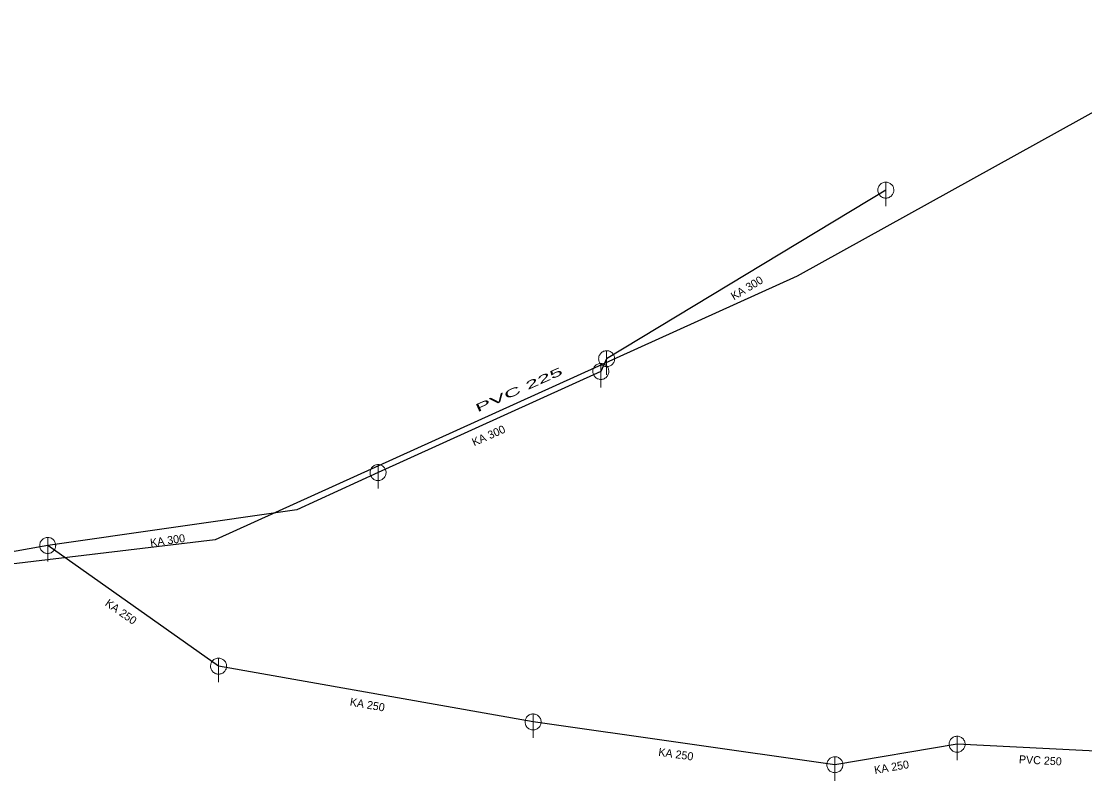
# Model space of a CAD drawing. Extents: x -659250 to -657316, y -997555 to -993684.
# Drawn here: x -658412.5 to -658279.6, y -995142.2 to -995047.3 of the extents above; entities that cross this region are included whole.
import ezdxf

# ---------------------------------------------------------------- set-up
doc = ezdxf.new("R2010")
doc.units = 0
doc.header["$LTSCALE"] = 0.4
doc.layers.add('1', color=7, linetype='Continuous')
for name, color, linetype, lineweight in [('14', 7, 'Continuous', 25), ('17', 7, 'Continuous', 25), ('22', 7, 'Continuous', 13)]:
    doc.layers.add(name, color=color, linetype=linetype, lineweight=lineweight)

msp = doc.modelspace()

# ---------------------------------------------------------------- linework, layer by layer
at = {"layer": '14'}
for p, q in [((-658304.458, -995068.407), (-658339.359, -995089.46)), ((-658339.359, -995089.46), (-658340.085, -995091.051)), ((-658340.085, -995091.051), (-658367.932, -995103.685)), ((-658409.23, -995112.789), (-658422.21, -995115.16)), ((-658272.949, -995138.75), (-658295.55, -995137.62))]:
    msp.add_line(p, q, dxfattribs=at)
for points in [[(-658367.932, -995103.685), (-658378.086, -995108.348), (-658409.23, -995112.789)], [(-658348.55, -995134.84), (-658387.87, -995127.87), (-658409.23, -995112.789)], [(-658295.55, -995137.62), (-658310.829, -995140.18), (-658348.55, -995134.84)]]:
    msp.add_lwpolyline(points, dxfattribs=at)
at = {"layer": '17'}
msp.add_lwpolyline([(-658259.263, -995047.311), (-658274.545, -995056.438), (-658315.531, -995079.142), (-658388.274, -995112.102), (-658418.381, -995115.664), (-658425.669, -995116.129), (-658489.359, -995122.5)], dxfattribs=at)
at = {"layer": '22'}
for p, q in [((-658304.459, -995070.407), (-658304.458, -995067.407)), ((-658339.359, -995091.46), (-658339.358, -995088.46)), ((-658340.085, -995093.051), (-658340.084, -995090.051)), ((-658367.932, -995105.685), (-658367.931, -995102.685)), ((-658409.23, -995114.79), (-658409.229, -995111.79)), ((-658387.87, -995129.87), (-658387.869, -995126.87)), ((-658348.55, -995136.84), (-658348.549, -995133.84)), ((-658295.55, -995139.62), (-658295.549, -995136.62)), ((-658310.83, -995142.18), (-658310.829, -995139.18))]:
    msp.add_line(p, q, dxfattribs=at)
for points in [[(-658303.459, -995068.407), (-658303.464, -995068.298), (-658303.482, -995068.19), (-658303.512, -995068.084), (-658303.552, -995067.983), (-658303.604, -995067.886), (-658303.666, -995067.796), (-658303.738, -995067.713), (-658303.818, -995067.639), (-658303.906, -995067.573), (-658304, -995067.518), (-658304.1, -995067.473), (-658304.205, -995067.44), (-658304.312, -995067.418), (-658304.421, -995067.408), (-658304.531, -995067.41), (-658304.639, -995067.424), (-658304.746, -995067.449), (-658304.849, -995067.486), (-658304.947, -995067.535), (-658305.039, -995067.593), (-658305.125, -995067.662), (-658305.202, -995067.739), (-658305.271, -995067.825), (-658305.33, -995067.917), (-658305.378, -995068.015), (-658305.415, -995068.118), (-658305.441, -995068.225), (-658305.455, -995068.333), (-658305.458, -995068.443), (-658305.448, -995068.552), (-658305.427, -995068.659), (-658305.393, -995068.763), (-658305.349, -995068.863), (-658305.294, -995068.958), (-658305.228, -995069.046), (-658305.154, -995069.126), (-658305.071, -995069.198), (-658304.981, -995069.26), (-658304.885, -995069.312), (-658304.783, -995069.353), (-658304.678, -995069.383), (-658304.57, -995069.401), (-658304.46, -995069.407), (-658304.351, -995069.401), (-658304.243, -995069.383), (-658304.138, -995069.354), (-658304.036, -995069.313), (-658303.939, -995069.261), (-658303.849, -995069.199), (-658303.766, -995069.128), (-658303.691, -995069.048), (-658303.626, -995068.96), (-658303.57, -995068.866), (-658303.526, -995068.766), (-658303.492, -995068.662), (-658303.47, -995068.554), (-658303.46, -995068.445)], [(-658338.359, -995089.46), (-658338.364, -995089.351), (-658338.382, -995089.243), (-658338.412, -995089.137), (-658338.452, -995089.036), (-658338.504, -995088.939), (-658338.566, -995088.849), (-658338.638, -995088.766), (-658338.718, -995088.692), (-658338.806, -995088.626), (-658338.9, -995088.571), (-658339, -995088.526), (-658339.105, -995088.493), (-658339.212, -995088.471), (-658339.321, -995088.461), (-658339.431, -995088.463), (-658339.539, -995088.477), (-658339.646, -995088.502), (-658339.749, -995088.539), (-658339.847, -995088.588), (-658339.939, -995088.646), (-658340.025, -995088.715), (-658340.102, -995088.792), (-658340.171, -995088.878), (-658340.23, -995088.97), (-658340.278, -995089.068), (-658340.315, -995089.171), (-658340.341, -995089.278), (-658340.355, -995089.386), (-658340.358, -995089.496), (-658340.348, -995089.605), (-658340.327, -995089.712), (-658340.293, -995089.816), (-658340.249, -995089.916), (-658340.194, -995090.011), (-658340.128, -995090.099), (-658340.054, -995090.179), (-658339.971, -995090.251), (-658339.881, -995090.313), (-658339.785, -995090.365), (-658339.683, -995090.406), (-658339.578, -995090.436), (-658339.47, -995090.454), (-658339.36, -995090.46), (-658339.251, -995090.454), (-658339.143, -995090.436), (-658339.038, -995090.407), (-658338.936, -995090.366), (-658338.839, -995090.314), (-658338.749, -995090.252), (-658338.666, -995090.181), (-658338.591, -995090.101), (-658338.526, -995090.013), (-658338.47, -995089.919), (-658338.426, -995089.819), (-658338.392, -995089.715), (-658338.37, -995089.607), (-658338.36, -995089.498)], [(-658339.085, -995091.051), (-658339.09, -995090.942), (-658339.108, -995090.834), (-658339.138, -995090.728), (-658339.178, -995090.627), (-658339.23, -995090.53), (-658339.292, -995090.44), (-658339.364, -995090.357), (-658339.444, -995090.283), (-658339.532, -995090.217), (-658339.626, -995090.162), (-658339.726, -995090.117), (-658339.831, -995090.084), (-658339.938, -995090.062), (-658340.047, -995090.052), (-658340.157, -995090.054), (-658340.265, -995090.068), (-658340.372, -995090.093), (-658340.475, -995090.13), (-658340.573, -995090.179), (-658340.665, -995090.237), (-658340.751, -995090.306), (-658340.828, -995090.383), (-658340.897, -995090.469), (-658340.956, -995090.561), (-658341.004, -995090.659), (-658341.041, -995090.762), (-658341.067, -995090.869), (-658341.081, -995090.977), (-658341.084, -995091.087), (-658341.074, -995091.196), (-658341.053, -995091.303), (-658341.019, -995091.407), (-658340.975, -995091.507), (-658340.92, -995091.602), (-658340.854, -995091.69), (-658340.78, -995091.77), (-658340.697, -995091.842), (-658340.607, -995091.904), (-658340.511, -995091.956), (-658340.409, -995091.997), (-658340.304, -995092.027), (-658340.196, -995092.045), (-658340.086, -995092.051), (-658339.977, -995092.045), (-658339.869, -995092.027), (-658339.764, -995091.998), (-658339.662, -995091.957), (-658339.565, -995091.905), (-658339.475, -995091.843), (-658339.392, -995091.772), (-658339.317, -995091.692), (-658339.252, -995091.604), (-658339.196, -995091.51), (-658339.152, -995091.41), (-658339.118, -995091.306), (-658339.096, -995091.198), (-658339.086, -995091.089)], [(-658366.932, -995103.685), (-658366.937, -995103.576), (-658366.955, -995103.468), (-658366.985, -995103.362), (-658367.025, -995103.261), (-658367.077, -995103.164), (-658367.139, -995103.074), (-658367.211, -995102.991), (-658367.291, -995102.917), (-658367.379, -995102.851), (-658367.473, -995102.796), (-658367.573, -995102.751), (-658367.678, -995102.718), (-658367.785, -995102.696), (-658367.894, -995102.686), (-658368.004, -995102.688), (-658368.112, -995102.702), (-658368.219, -995102.727), (-658368.322, -995102.764), (-658368.42, -995102.813), (-658368.512, -995102.871), (-658368.598, -995102.94), (-658368.675, -995103.017), (-658368.744, -995103.103), (-658368.803, -995103.195), (-658368.851, -995103.293), (-658368.888, -995103.396), (-658368.914, -995103.503), (-658368.928, -995103.611), (-658368.931, -995103.721), (-658368.921, -995103.83), (-658368.9, -995103.937), (-658368.866, -995104.041), (-658368.822, -995104.141), (-658368.767, -995104.236), (-658368.701, -995104.324), (-658368.627, -995104.404), (-658368.544, -995104.476), (-658368.454, -995104.538), (-658368.358, -995104.59), (-658368.256, -995104.631), (-658368.151, -995104.661), (-658368.043, -995104.679), (-658367.933, -995104.685), (-658367.824, -995104.679), (-658367.716, -995104.661), (-658367.611, -995104.632), (-658367.509, -995104.591), (-658367.412, -995104.539), (-658367.322, -995104.477), (-658367.239, -995104.406), (-658367.164, -995104.326), (-658367.099, -995104.238), (-658367.043, -995104.144), (-658366.999, -995104.044), (-658366.965, -995103.94), (-658366.943, -995103.832), (-658366.933, -995103.723)], [(-658408.23, -995112.79), (-658408.235, -995112.681), (-658408.253, -995112.573), (-658408.283, -995112.467), (-658408.323, -995112.366), (-658408.375, -995112.269), (-658408.437, -995112.179), (-658408.509, -995112.096), (-658408.589, -995112.022), (-658408.677, -995111.956), (-658408.771, -995111.901), (-658408.871, -995111.856), (-658408.976, -995111.823), (-658409.083, -995111.801), (-658409.192, -995111.791), (-658409.302, -995111.793), (-658409.41, -995111.807), (-658409.517, -995111.832), (-658409.62, -995111.869), (-658409.718, -995111.918), (-658409.81, -995111.976), (-658409.896, -995112.045), (-658409.973, -995112.122), (-658410.042, -995112.208), (-658410.101, -995112.3), (-658410.149, -995112.398), (-658410.186, -995112.501), (-658410.212, -995112.608), (-658410.226, -995112.716), (-658410.229, -995112.826), (-658410.219, -995112.935), (-658410.198, -995113.042), (-658410.164, -995113.146), (-658410.12, -995113.246), (-658410.065, -995113.341), (-658409.999, -995113.429), (-658409.925, -995113.509), (-658409.842, -995113.581), (-658409.752, -995113.643), (-658409.656, -995113.695), (-658409.554, -995113.736), (-658409.449, -995113.766), (-658409.341, -995113.784), (-658409.231, -995113.79), (-658409.122, -995113.784), (-658409.014, -995113.766), (-658408.909, -995113.737), (-658408.807, -995113.696), (-658408.71, -995113.644), (-658408.62, -995113.582), (-658408.537, -995113.511), (-658408.462, -995113.431), (-658408.397, -995113.343), (-658408.341, -995113.249), (-658408.297, -995113.149), (-658408.263, -995113.045), (-658408.241, -995112.937), (-658408.231, -995112.828)], [(-658386.87, -995127.87), (-658386.875, -995127.761), (-658386.893, -995127.653), (-658386.923, -995127.547), (-658386.963, -995127.446), (-658387.015, -995127.349), (-658387.077, -995127.259), (-658387.149, -995127.176), (-658387.229, -995127.102), (-658387.317, -995127.036), (-658387.411, -995126.981), (-658387.511, -995126.936), (-658387.616, -995126.903), (-658387.723, -995126.881), (-658387.832, -995126.871), (-658387.942, -995126.873), (-658388.05, -995126.887), (-658388.157, -995126.912), (-658388.26, -995126.949), (-658388.358, -995126.998), (-658388.45, -995127.056), (-658388.536, -995127.125), (-658388.613, -995127.202), (-658388.682, -995127.288), (-658388.741, -995127.38), (-658388.789, -995127.478), (-658388.826, -995127.581), (-658388.852, -995127.688), (-658388.866, -995127.796), (-658388.869, -995127.906), (-658388.859, -995128.015), (-658388.838, -995128.122), (-658388.804, -995128.226), (-658388.76, -995128.326), (-658388.705, -995128.421), (-658388.639, -995128.509), (-658388.565, -995128.589), (-658388.482, -995128.661), (-658388.392, -995128.723), (-658388.296, -995128.775), (-658388.194, -995128.816), (-658388.089, -995128.846), (-658387.981, -995128.864), (-658387.871, -995128.87), (-658387.762, -995128.864), (-658387.654, -995128.846), (-658387.549, -995128.817), (-658387.447, -995128.776), (-658387.35, -995128.724), (-658387.26, -995128.662), (-658387.177, -995128.591), (-658387.102, -995128.511), (-658387.037, -995128.423), (-658386.981, -995128.329), (-658386.937, -995128.229), (-658386.903, -995128.125), (-658386.881, -995128.017), (-658386.871, -995127.908)], [(-658347.55, -995134.84), (-658347.555, -995134.731), (-658347.573, -995134.623), (-658347.603, -995134.517), (-658347.643, -995134.416), (-658347.695, -995134.319), (-658347.757, -995134.229), (-658347.829, -995134.146), (-658347.909, -995134.072), (-658347.997, -995134.006), (-658348.091, -995133.951), (-658348.191, -995133.906), (-658348.296, -995133.873), (-658348.403, -995133.851), (-658348.512, -995133.841), (-658348.622, -995133.843), (-658348.73, -995133.857), (-658348.837, -995133.882), (-658348.94, -995133.919), (-658349.038, -995133.968), (-658349.13, -995134.026), (-658349.216, -995134.095), (-658349.293, -995134.172), (-658349.362, -995134.258), (-658349.421, -995134.35), (-658349.469, -995134.448), (-658349.506, -995134.551), (-658349.532, -995134.658), (-658349.546, -995134.766), (-658349.549, -995134.876), (-658349.539, -995134.985), (-658349.518, -995135.092), (-658349.484, -995135.196), (-658349.44, -995135.296), (-658349.385, -995135.391), (-658349.319, -995135.479), (-658349.245, -995135.559), (-658349.162, -995135.631), (-658349.072, -995135.693), (-658348.976, -995135.745), (-658348.874, -995135.786), (-658348.769, -995135.816), (-658348.661, -995135.834), (-658348.551, -995135.84), (-658348.442, -995135.834), (-658348.334, -995135.816), (-658348.229, -995135.787), (-658348.127, -995135.746), (-658348.03, -995135.694), (-658347.94, -995135.632), (-658347.857, -995135.561), (-658347.782, -995135.481), (-658347.717, -995135.393), (-658347.661, -995135.299), (-658347.617, -995135.199), (-658347.583, -995135.095), (-658347.561, -995134.987), (-658347.551, -995134.878)], [(-658294.55, -995137.62), (-658294.555, -995137.511), (-658294.573, -995137.403), (-658294.603, -995137.297), (-658294.643, -995137.196), (-658294.695, -995137.099), (-658294.757, -995137.009), (-658294.829, -995136.926), (-658294.909, -995136.852), (-658294.997, -995136.786), (-658295.091, -995136.731), (-658295.191, -995136.686), (-658295.296, -995136.653), (-658295.403, -995136.631), (-658295.512, -995136.621), (-658295.622, -995136.623), (-658295.73, -995136.637), (-658295.837, -995136.662), (-658295.94, -995136.699), (-658296.038, -995136.748), (-658296.13, -995136.806), (-658296.216, -995136.875), (-658296.293, -995136.952), (-658296.362, -995137.038), (-658296.421, -995137.13), (-658296.469, -995137.228), (-658296.506, -995137.331), (-658296.532, -995137.438), (-658296.546, -995137.546), (-658296.549, -995137.656), (-658296.539, -995137.765), (-658296.518, -995137.872), (-658296.484, -995137.976), (-658296.44, -995138.076), (-658296.385, -995138.171), (-658296.319, -995138.259), (-658296.245, -995138.339), (-658296.162, -995138.411), (-658296.072, -995138.473), (-658295.976, -995138.525), (-658295.874, -995138.566), (-658295.769, -995138.596), (-658295.661, -995138.614), (-658295.551, -995138.62), (-658295.442, -995138.614), (-658295.334, -995138.596), (-658295.229, -995138.567), (-658295.127, -995138.526), (-658295.03, -995138.474), (-658294.94, -995138.412), (-658294.857, -995138.341), (-658294.782, -995138.261), (-658294.717, -995138.173), (-658294.661, -995138.079), (-658294.617, -995137.979), (-658294.583, -995137.875), (-658294.561, -995137.767), (-658294.551, -995137.658)], [(-658309.83, -995140.18), (-658309.835, -995140.071), (-658309.853, -995139.963), (-658309.883, -995139.857), (-658309.923, -995139.756), (-658309.975, -995139.659), (-658310.037, -995139.569), (-658310.109, -995139.486), (-658310.189, -995139.412), (-658310.277, -995139.346), (-658310.371, -995139.291), (-658310.471, -995139.246), (-658310.576, -995139.213), (-658310.683, -995139.191), (-658310.792, -995139.181), (-658310.902, -995139.183), (-658311.01, -995139.197), (-658311.117, -995139.222), (-658311.22, -995139.259), (-658311.318, -995139.308), (-658311.41, -995139.366), (-658311.496, -995139.435), (-658311.573, -995139.512), (-658311.642, -995139.598), (-658311.701, -995139.69), (-658311.749, -995139.788), (-658311.786, -995139.891), (-658311.812, -995139.998), (-658311.826, -995140.106), (-658311.829, -995140.216), (-658311.819, -995140.325), (-658311.798, -995140.432), (-658311.764, -995140.536), (-658311.72, -995140.636), (-658311.665, -995140.731), (-658311.599, -995140.819), (-658311.525, -995140.899), (-658311.442, -995140.971), (-658311.352, -995141.033), (-658311.256, -995141.085), (-658311.154, -995141.126), (-658311.049, -995141.156), (-658310.941, -995141.174), (-658310.831, -995141.18), (-658310.722, -995141.174), (-658310.614, -995141.156), (-658310.509, -995141.127), (-658310.407, -995141.086), (-658310.31, -995141.034), (-658310.22, -995140.972), (-658310.137, -995140.901), (-658310.062, -995140.821), (-658309.997, -995140.733), (-658309.941, -995140.639), (-658309.897, -995140.539), (-658309.863, -995140.435), (-658309.841, -995140.327), (-658309.831, -995140.218)]]:
    msp.add_lwpolyline(points, close=True, dxfattribs=at)

# ---------------------------------------------------------------- texts
at = {"layer": '1'}
for s, rotation, p in [('KA 300', 31, (-658323.452, -995082.182)), ('KA 300', 24, (-658355.92, -995100.415)), ('KA 300', 8, (-658396.347, -995112.957)), ('KA 250', 325, (-658402.145, -995120.221)), ('KA 250', 350, (-658371.51, -995132.785)), ('KA 250', 352, (-658332.938, -995139.054)), ('PVC 250 ', 357, (-658287.844, -995139.992)), ('KA 250', 10, (-658305.82, -995141.352))]:
    msp.add_text(s, height=1, rotation=rotation, dxfattribs=at).set_placement(p)
at = {"layer": '1', "width": 2.2}
msp.add_text('PVC 225 ', height=1, rotation=24, dxfattribs=at).set_placement((-658355.496, -995096.168))

doc.saveas('drawing.dxf')
